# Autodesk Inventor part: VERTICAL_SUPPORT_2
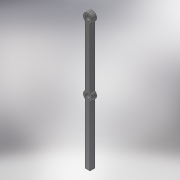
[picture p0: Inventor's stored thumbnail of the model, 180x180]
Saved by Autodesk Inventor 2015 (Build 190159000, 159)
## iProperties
Created: 2014-08
Part Number: VERTICAL_SUPPORT_2
Material: Steel, Mild
Document SubType Name: Modeling
Designer: lakshayg
Density: 7.85 g/cm^3
Appearance: Semi-Polished
Mass: 392.351 g
Surface Area: 179.727 cm^2
Volume: 49.981 cm^3
Author: lakshayg
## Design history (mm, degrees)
sketch "Sketch1"
  geometry: L1 (6, -333.349)-(-6, -333.349); L2 (-6, -9.516)-(-6, -161.916); L3 (-6, -180.949)-(-6, -333.349); L4 (6, -9.516)-(6, -161.916); L5 (6, -180.949)-(6, -333.349); L6 (0, 0)-(0, -171.433); C1 r 6.25 at (0, 0); C2 r 6.25 at (0, -171.433); A1 r 11.25 centre (0, 0) between (6, -9.516) and (-6, -9.516); A2 r 11.25 centre (0, -171.433) between (-6, -161.916) and (-6, -180.949); A3 r 11.25 centre (0, -171.433) between (6, -180.949) and (6, -161.916); 1 further point
  constraints: 12 end point, 6 point on circle, 5 centre point, 3 coincident, 3 equal radius, 1 collinear, 1 horizontal, 1 parallel, 1 vertical, 3 other
  dimensions: "d10" = 12 distance between parallel lines of L2 L4; "d17" = 152.4 distance of L2.end L2.start; "d19" = 152.4 distance of L3.start L1.end; "d20" = 5 radial gap between concentric circles of A1 C1; "d21" = 12.5 diameter of C1
extrude "Extrusion1" new body sketch "Sketch1" distance "d15" = 12; taper "d16" = 0 deg
body "Solid1"
